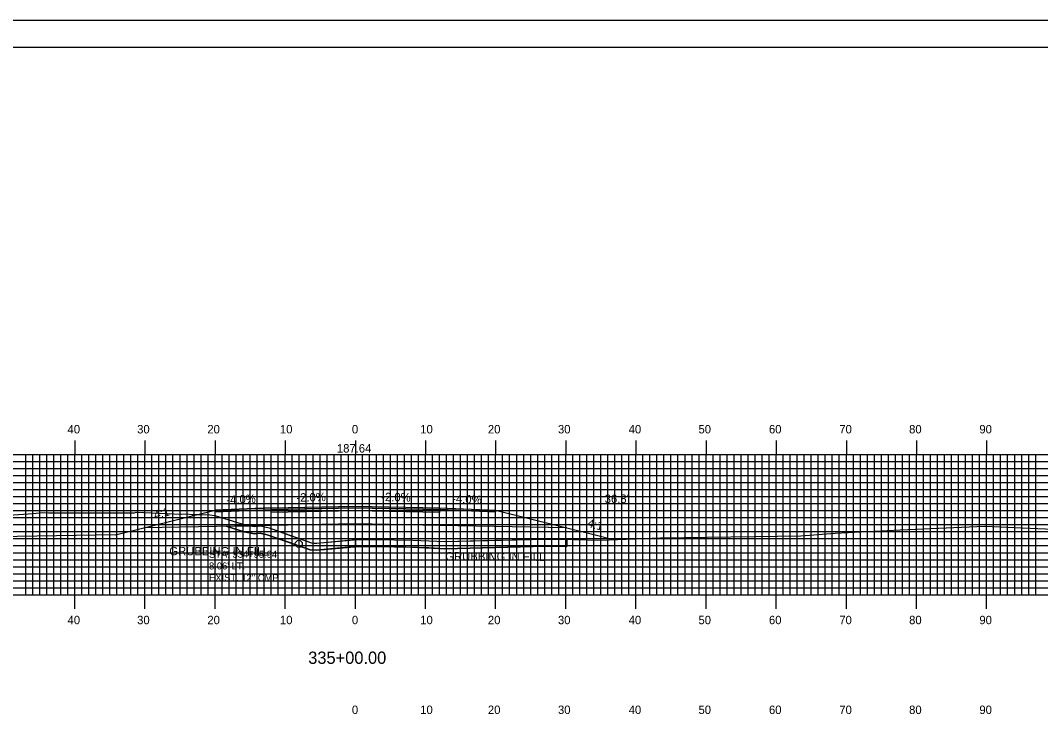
# Model space of a CAD drawing. Extents: x 1823179 to 1823522, y 442591 to 442811.
# Drawn here: x 1823297 to 1823442.5, y 442711.2 to 442810.5 of the extents above; entities that cross this region are included whole.
import ezdxf

# ---------------------------------------------------------------- set-up
doc = ezdxf.new("R2010")
doc.units = 0
for name, color, linetype in [('ANNOTATION', 7, 'Continuous'), ('BORDER', 7, 'Continuous'), ('D_Drainage_Culvert', 7, 'Continuous'), ('D_Roadway_Centerline', 7, 'Continuous'), ('D_Roadway_Centerline_Text', 7, 'Continuous'), ('D_Roadway_Edge_Shoulder', 7, 'Continuous'), ('D_Roadway_Edge_TW', 7, 'Continuous'), ('D_Roadway_FinishedGrade', 7, 'Continuous'), ('D_Roadway_Pavement', 7, 'Continuous'), ('D_Roadway_SlopeLines', 7, 'Continuous'), ('D_Roadway_SubGrade', 7, 'Continuous'), ('D_Text_Monospaced', 7, 'Continuous'), ('D_Text_Standard', 7, 'Continuous'), ('GRUBBING IN FILL', 7, 'Continuous'), ('H_V ANNOTATION', 7, 'Continuous'), ('MAJOR', 7, 'Continuous'), ('MINOR', 7, 'Continuous'), ('PLOT BOUNDARY', 7, 'Continuous'), ('S_Roadway_Centerline', 7, 'Continuous')]:
    doc.layers.add(name, color=color, linetype=linetype)

msp = doc.modelspace()

# ---------------------------------------------------------------- linework, layer by layer
at = {"layer": 'BORDER'}
msp.add_lwpolyline([(1823195.2, 442596.67), (1823515.2, 442596.67), (1823515.2, 442806.67), (1823195.2, 442806.67)], close=True, dxfattribs=at)
at = {"layer": 'D_Drainage_Culvert'}
msp.add_circle((1823336.74, 442735.93), 0.5, dxfattribs=at)
at = {"layer": 'D_Roadway_Centerline'}
msp.add_lwpolyline([(1823310.62, 442737.2), (1823314.62, 442738.2), (1823324.8, 442740.74), (1823332.8, 442741.06), (1823344.8, 442741.3), (1823356.8, 442741.06), (1823364.8, 442740.74), (1823374.97, 442738.2), (1823378.97, 442737.2), (1823381.61, 442736.54)], dxfattribs=at)
at = {"layer": 'D_Roadway_Edge_Shoulder'}
for points in [[(1823332.8, 442741.06), (1823324.8, 442740.74), (1823324.8, 442740.49), (1823332.8, 442740.81)], [(1823356.8, 442741.06), (1823364.8, 442740.74), (1823364.8, 442740.49), (1823356.8, 442740.81)]]:
    msp.add_lwpolyline(points, close=True, dxfattribs=at)
at = {"layer": 'D_Roadway_Edge_TW'}
msp.add_lwpolyline([(1823332.8, 442740.81), (1823332.8, 442741.06), (1823344.8, 442741.3), (1823356.8, 442741.06), (1823356.8, 442740.81), (1823344.8, 442741.05)], close=True, dxfattribs=at)
at = {"layer": 'D_Roadway_FinishedGrade'}
msp.add_line((1823310.62, 442737.2), (1823264.23, 442736.46), dxfattribs=at)
at = {"layer": 'D_Roadway_Pavement'}
msp.add_lwpolyline([(1823332.8, 442740.39), (1823332.8, 442740.81), (1823344.8, 442741.05), (1823356.8, 442740.81), (1823356.8, 442740.39), (1823344.8, 442740.63)], close=True, dxfattribs=at)
at = {"layer": 'D_Roadway_SlopeLines'}
msp.add_lwpolyline([(1823364.8, 442740.74), (1823378.97, 442737.2), (1823381.61, 442736.54)], dxfattribs=at)
at = {"layer": 'D_Roadway_SubGrade'}
msp.add_lwpolyline([(1823332.8, 442738.56), (1823314.62, 442738.2), (1823324.8, 442740.74), (1823324.8, 442740.49), (1823332.8, 442740.81), (1823344.8, 442741.05), (1823356.8, 442740.81), (1823364.8, 442740.49), (1823364.8, 442740.74), (1823374.97, 442738.2), (1823356.8, 442738.56), (1823344.8, 442738.8)], close=True, dxfattribs=at)
at = {"layer": 'GRUBBING IN FILL'}
msp.add_line((1823374.97, 442736.57), (1823374.97, 442735.57), dxfattribs=at)
msp.add_line((1823374.97, 442736.57), (1823374.97, 442735.57), dxfattribs=at)
for points in [[(1823326.37, 442738.43), (1823329.8, 442738.5), (1823330.47, 442738.38), (1823330.88, 442738.43), (1823331.29, 442738.48), (1823331.9, 442738.33), (1823332.51, 442738.19), (1823335.53, 442737.13), (1823338.55, 442736.06), (1823338.93, 442736.04), (1823339.32, 442736.01), (1823344.8, 442736.53), (1823344.8, 442735.53), (1823342.27, 442735.29), (1823339.33, 442735.01), (1823338.34, 442735.07), (1823335.29, 442736.15), (1823332.23, 442737.23), (1823331.23, 442737.46), (1823330.44, 442737.37), (1823328.97, 442737.63)], [(1823326.37, 442738.43), (1823329.8, 442738.5), (1823330.47, 442738.38), (1823330.88, 442738.43), (1823331.29, 442738.48), (1823331.9, 442738.33), (1823332.51, 442738.19), (1823335.53, 442737.13), (1823338.55, 442736.06), (1823338.93, 442736.04), (1823339.32, 442736.01), (1823344.8, 442736.53), (1823344.8, 442735.53), (1823342.27, 442735.29), (1823339.33, 442735.01), (1823338.34, 442735.07), (1823335.29, 442736.15), (1823332.23, 442737.23), (1823331.23, 442737.46), (1823330.44, 442737.37), (1823328.97, 442737.63)], [(1823344.8, 442736.53), (1823346.48, 442736.56), (1823350.4, 442736.5), (1823353, 442736.45), (1823355.28, 442736.35), (1823357.56, 442736.24), (1823364.75, 442736.43), (1823371.94, 442736.61), (1823374.04, 442736.6), (1823374.97, 442736.57), (1823374.97, 442735.57), (1823374.02, 442735.6), (1823371.95, 442735.61), (1823364.75, 442735.43), (1823357.55, 442735.24), (1823355.26, 442735.35), (1823350.38, 442735.5), (1823345.2, 442735.57), (1823344.8, 442735.53)], [(1823344.8, 442736.53), (1823346.48, 442736.56), (1823350.4, 442736.5), (1823353, 442736.45), (1823355.28, 442736.35), (1823357.56, 442736.24), (1823364.75, 442736.43), (1823371.94, 442736.61), (1823374.04, 442736.6), (1823374.97, 442736.57), (1823374.97, 442735.57), (1823374.02, 442735.6), (1823371.95, 442735.61), (1823364.75, 442735.43), (1823357.55, 442735.24), (1823355.26, 442735.35), (1823350.38, 442735.5), (1823345.2, 442735.57), (1823344.8, 442735.53)]]:
    msp.add_lwpolyline(points, close=True, dxfattribs=at)
msp.add_lwpolyline([(1823326.37, 442738.43), (1823328.97, 442737.63), (1823330.44, 442737.37), (1823331.23, 442737.46), (1823332.23, 442737.23), (1823338.34, 442735.07), (1823339.33, 442735.01), (1823345.2, 442735.57), (1823347.79, 442735.55), (1823352.97, 442735.45), (1823357.55, 442735.24), (1823371.95, 442735.61), (1823374.02, 442735.6), (1823374.97, 442735.57)], dxfattribs=at)
msp.add_lwpolyline([(1823326.37, 442738.43), (1823328.97, 442737.63), (1823330.44, 442737.37), (1823331.23, 442737.46), (1823332.23, 442737.23), (1823338.34, 442735.07), (1823339.33, 442735.01), (1823345.2, 442735.57), (1823347.79, 442735.55), (1823352.97, 442735.45), (1823357.55, 442735.24), (1823371.95, 442735.61), (1823374.02, 442735.6), (1823374.97, 442735.57)], dxfattribs=at)
at = {"layer": 'MAJOR'}
for p, q in [((1823304.8, 442750.67), (1823304.8, 442748.67)), ((1823314.8, 442750.67), (1823314.8, 442748.67)), ((1823324.8, 442750.67), (1823324.8, 442748.67)), ((1823334.8, 442750.67), (1823334.8, 442748.67)), ((1823344.8, 442750.67), (1823344.8, 442748.67)), ((1823354.8, 442750.67), (1823354.8, 442748.67)), ((1823364.8, 442750.67), (1823364.8, 442748.67)), ((1823374.8, 442750.67), (1823374.8, 442748.67)), ((1823384.8, 442750.67), (1823384.8, 442748.67)), ((1823394.8, 442750.67), (1823394.8, 442748.67)), ((1823404.8, 442750.67), (1823404.8, 442748.67)), ((1823414.8, 442750.67), (1823414.8, 442748.67)), ((1823424.8, 442750.67), (1823424.8, 442748.67)), ((1823434.8, 442750.67), (1823434.8, 442748.67)), ((1823204.8, 442748.67), (1823484.8, 442748.67)), ((1823204.8, 442748.67), (1823484.8, 442748.67)), ((1823304.8, 442728.67), (1823304.8, 442748.67)), ((1823314.8, 442728.67), (1823314.8, 442748.67)), ((1823324.8, 442728.67), (1823324.8, 442748.67)), ((1823334.8, 442728.67), (1823334.8, 442748.67)), ((1823344.8, 442728.67), (1823344.8, 442748.67)), ((1823354.8, 442728.67), (1823354.8, 442748.67)), ((1823364.8, 442728.67), (1823364.8, 442748.67)), ((1823374.8, 442728.67), (1823374.8, 442748.67)), ((1823384.8, 442728.67), (1823384.8, 442748.67)), ((1823394.8, 442728.67), (1823394.8, 442748.67)), ((1823404.8, 442728.67), (1823404.8, 442748.67)), ((1823414.8, 442728.67), (1823414.8, 442748.67)), ((1823424.8, 442728.67), (1823424.8, 442748.67)), ((1823434.8, 442728.67), (1823434.8, 442748.67)), ((1823204.8, 442743.67), (1823484.8, 442743.67)), ((1823204.8, 442738.67), (1823484.8, 442738.67)), ((1823204.8, 442733.67), (1823484.8, 442733.67)), ((1823204.8, 442728.67), (1823484.8, 442728.67)), ((1823204.8, 442728.67), (1823484.8, 442728.67)), ((1823304.8, 442726.66), (1823304.8, 442728.67)), ((1823314.8, 442726.66), (1823314.8, 442728.67)), ((1823324.8, 442726.66), (1823324.8, 442728.67)), ((1823334.8, 442726.66), (1823334.8, 442728.67)), ((1823344.8, 442726.66), (1823344.8, 442728.67)), ((1823354.8, 442726.66), (1823354.8, 442728.67)), ((1823364.8, 442726.66), (1823364.8, 442728.67)), ((1823374.8, 442726.66), (1823374.8, 442728.67)), ((1823384.8, 442726.66), (1823384.8, 442728.67)), ((1823394.8, 442726.66), (1823394.8, 442728.67)), ((1823404.8, 442726.66), (1823404.8, 442728.67)), ((1823414.8, 442726.66), (1823414.8, 442728.67)), ((1823424.8, 442726.66), (1823424.8, 442728.67)), ((1823434.8, 442726.66), (1823434.8, 442728.67))]:
    msp.add_line(p, q, dxfattribs=at)
at = {"layer": 'MINOR'}
for p, q in [((1823297.8, 442728.67), (1823297.8, 442748.67)), ((1823298.8, 442728.67), (1823298.8, 442748.67)), ((1823299.8, 442728.67), (1823299.8, 442748.67)), ((1823300.8, 442728.67), (1823300.8, 442748.67)), ((1823301.8, 442728.67), (1823301.8, 442748.67)), ((1823302.8, 442728.67), (1823302.8, 442748.67)), ((1823303.8, 442728.67), (1823303.8, 442748.67)), ((1823305.8, 442728.67), (1823305.8, 442748.67)), ((1823306.8, 442728.67), (1823306.8, 442748.67)), ((1823307.8, 442728.67), (1823307.8, 442748.67)), ((1823308.8, 442728.67), (1823308.8, 442748.67)), ((1823309.8, 442728.67), (1823309.8, 442748.67)), ((1823310.8, 442728.67), (1823310.8, 442748.67)), ((1823311.8, 442728.67), (1823311.8, 442748.67)), ((1823312.8, 442728.67), (1823312.8, 442748.67)), ((1823313.8, 442728.67), (1823313.8, 442748.67)), ((1823315.8, 442728.67), (1823315.8, 442748.67)), ((1823316.8, 442728.67), (1823316.8, 442748.67)), ((1823317.8, 442728.67), (1823317.8, 442748.67)), ((1823318.8, 442728.67), (1823318.8, 442748.67)), ((1823319.8, 442728.67), (1823319.8, 442748.67)), ((1823320.8, 442728.67), (1823320.8, 442748.67)), ((1823321.8, 442728.67), (1823321.8, 442748.67)), ((1823322.8, 442728.67), (1823322.8, 442748.67)), ((1823323.8, 442728.67), (1823323.8, 442748.67)), ((1823325.8, 442728.67), (1823325.8, 442748.67)), ((1823326.8, 442728.67), (1823326.8, 442748.67)), ((1823327.8, 442728.67), (1823327.8, 442748.67)), ((1823328.8, 442728.67), (1823328.8, 442748.67)), ((1823329.8, 442728.67), (1823329.8, 442748.67)), ((1823330.8, 442728.67), (1823330.8, 442748.67)), ((1823331.8, 442728.67), (1823331.8, 442748.67)), ((1823332.8, 442728.67), (1823332.8, 442748.67)), ((1823333.8, 442728.67), (1823333.8, 442748.67)), ((1823335.8, 442728.67), (1823335.8, 442748.67)), ((1823336.8, 442728.67), (1823336.8, 442748.67)), ((1823337.8, 442728.67), (1823337.8, 442748.67)), ((1823338.8, 442728.67), (1823338.8, 442748.67)), ((1823339.8, 442728.67), (1823339.8, 442748.67)), ((1823340.8, 442728.67), (1823340.8, 442748.67)), ((1823341.8, 442728.67), (1823341.8, 442748.67)), ((1823342.8, 442728.67), (1823342.8, 442748.67)), ((1823343.8, 442728.67), (1823343.8, 442748.67)), ((1823345.8, 442728.67), (1823345.8, 442748.67)), ((1823346.8, 442728.67), (1823346.8, 442748.67)), ((1823347.8, 442728.67), (1823347.8, 442748.67)), ((1823348.8, 442728.67), (1823348.8, 442748.67)), ((1823349.8, 442728.67), (1823349.8, 442748.67)), ((1823350.8, 442728.67), (1823350.8, 442748.67)), ((1823351.8, 442728.67), (1823351.8, 442748.67)), ((1823352.8, 442728.67), (1823352.8, 442748.67)), ((1823353.8, 442728.67), (1823353.8, 442748.67)), ((1823355.8, 442728.67), (1823355.8, 442748.67)), ((1823356.8, 442728.67), (1823356.8, 442748.67)), ((1823357.8, 442728.67), (1823357.8, 442748.67)), ((1823358.8, 442728.67), (1823358.8, 442748.67)), ((1823359.8, 442728.67), (1823359.8, 442748.67)), ((1823360.8, 442728.67), (1823360.8, 442748.67)), ((1823361.8, 442728.67), (1823361.8, 442748.67)), ((1823362.8, 442728.67), (1823362.8, 442748.67)), ((1823363.8, 442728.67), (1823363.8, 442748.67)), ((1823365.8, 442728.67), (1823365.8, 442748.67)), ((1823366.8, 442728.67), (1823366.8, 442748.67)), ((1823367.8, 442728.67), (1823367.8, 442748.67)), ((1823368.8, 442728.67), (1823368.8, 442748.67)), ((1823369.8, 442728.67), (1823369.8, 442748.67)), ((1823370.8, 442728.67), (1823370.8, 442748.67)), ((1823371.8, 442728.67), (1823371.8, 442748.67)), ((1823372.8, 442728.67), (1823372.8, 442748.67)), ((1823373.8, 442728.67), (1823373.8, 442748.67)), ((1823375.8, 442728.67), (1823375.8, 442748.67)), ((1823376.8, 442728.67), (1823376.8, 442748.67)), ((1823377.8, 442728.67), (1823377.8, 442748.67)), ((1823378.8, 442728.67), (1823378.8, 442748.67)), ((1823379.8, 442728.67), (1823379.8, 442748.67)), ((1823380.8, 442728.67), (1823380.8, 442748.67)), ((1823381.8, 442728.67), (1823381.8, 442748.67)), ((1823382.8, 442728.67), (1823382.8, 442748.67)), ((1823383.8, 442728.67), (1823383.8, 442748.67)), ((1823385.8, 442728.67), (1823385.8, 442748.67)), ((1823386.8, 442728.67), (1823386.8, 442748.67)), ((1823387.8, 442728.67), (1823387.8, 442748.67)), ((1823388.8, 442728.67), (1823388.8, 442748.67)), ((1823389.8, 442728.67), (1823389.8, 442748.67)), ((1823390.8, 442728.67), (1823390.8, 442748.67)), ((1823391.8, 442728.67), (1823391.8, 442748.67)), ((1823392.8, 442728.67), (1823392.8, 442748.67)), ((1823393.8, 442728.67), (1823393.8, 442748.67)), ((1823395.8, 442728.67), (1823395.8, 442748.67)), ((1823396.8, 442728.67), (1823396.8, 442748.67)), ((1823397.8, 442728.67), (1823397.8, 442748.67)), ((1823398.8, 442728.67), (1823398.8, 442748.67)), ((1823399.8, 442728.67), (1823399.8, 442748.67)), ((1823400.8, 442728.67), (1823400.8, 442748.67)), ((1823401.8, 442728.67), (1823401.8, 442748.67)), ((1823402.8, 442728.67), (1823402.8, 442748.67)), ((1823403.8, 442728.67), (1823403.8, 442748.67)), ((1823405.8, 442728.67), (1823405.8, 442748.67)), ((1823406.8, 442728.67), (1823406.8, 442748.67)), ((1823407.8, 442728.67), (1823407.8, 442748.67)), ((1823408.8, 442728.67), (1823408.8, 442748.67)), ((1823409.8, 442728.67), (1823409.8, 442748.67)), ((1823410.8, 442728.67), (1823410.8, 442748.67)), ((1823411.8, 442728.67), (1823411.8, 442748.67)), ((1823412.8, 442728.67), (1823412.8, 442748.67)), ((1823413.8, 442728.67), (1823413.8, 442748.67)), ((1823415.8, 442728.67), (1823415.8, 442748.67)), ((1823416.8, 442728.67), (1823416.8, 442748.67)), ((1823417.8, 442728.67), (1823417.8, 442748.67)), ((1823418.8, 442728.67), (1823418.8, 442748.67)), ((1823419.8, 442728.67), (1823419.8, 442748.67)), ((1823420.8, 442728.67), (1823420.8, 442748.67)), ((1823421.8, 442728.67), (1823421.8, 442748.67)), ((1823422.8, 442728.67), (1823422.8, 442748.67)), ((1823423.8, 442728.67), (1823423.8, 442748.67)), ((1823425.8, 442728.67), (1823425.8, 442748.67)), ((1823426.8, 442728.67), (1823426.8, 442748.67)), ((1823427.8, 442728.67), (1823427.8, 442748.67)), ((1823428.8, 442728.67), (1823428.8, 442748.67)), ((1823429.8, 442728.67), (1823429.8, 442748.67)), ((1823430.8, 442728.67), (1823430.8, 442748.67)), ((1823431.8, 442728.67), (1823431.8, 442748.67)), ((1823432.8, 442728.67), (1823432.8, 442748.67)), ((1823433.8, 442728.67), (1823433.8, 442748.67)), ((1823435.8, 442728.67), (1823435.8, 442748.67)), ((1823436.8, 442728.67), (1823436.8, 442748.67)), ((1823437.8, 442728.67), (1823437.8, 442748.67)), ((1823438.8, 442728.67), (1823438.8, 442748.67)), ((1823439.8, 442728.67), (1823439.8, 442748.67)), ((1823440.8, 442728.67), (1823440.8, 442748.67)), ((1823441.8, 442728.67), (1823441.8, 442748.67)), ((1823204.8, 442747.67), (1823484.8, 442747.67)), ((1823204.8, 442746.67), (1823484.8, 442746.67)), ((1823204.8, 442745.67), (1823484.8, 442745.67)), ((1823204.8, 442744.67), (1823484.8, 442744.67)), ((1823204.8, 442742.67), (1823484.8, 442742.67)), ((1823204.8, 442741.67), (1823484.8, 442741.67)), ((1823204.8, 442740.67), (1823484.8, 442740.67)), ((1823204.8, 442739.67), (1823484.8, 442739.67)), ((1823204.8, 442737.67), (1823484.8, 442737.67)), ((1823204.8, 442736.67), (1823484.8, 442736.67)), ((1823204.8, 442735.67), (1823484.8, 442735.67)), ((1823204.8, 442734.67), (1823484.8, 442734.67)), ((1823204.8, 442732.67), (1823484.8, 442732.67)), ((1823204.8, 442731.67), (1823484.8, 442731.67)), ((1823204.8, 442730.67), (1823484.8, 442730.67)), ((1823204.8, 442729.67), (1823484.8, 442729.67))]:
    msp.add_line(p, q, dxfattribs=at)
at = {"layer": 'PLOT BOUNDARY'}
msp.add_lwpolyline([(1823179.01, 442590.55), (1823519.01, 442590.55), (1823519.01, 442810.55), (1823179.01, 442810.55)], close=True, dxfattribs=at)
at = {"layer": 'S_Roadway_Centerline'}
msp.add_lwpolyline([(1823294.66, 442739.97), (1823298.87, 442740.23), (1823300.14, 442740.4), (1823301.04, 442740.37), (1823309.53, 442740.33), (1823313.29, 442740.36), (1823313.55, 442740.46), (1823314.64, 442740.4), (1823320, 442740.18), (1823320.79, 442740.19), (1823321.48, 442740.1), (1823322.3, 442740.1), (1823324.03, 442740.06), (1823324.76, 442739.98), (1823329.21, 442738.6), (1823330.47, 442738.38), (1823331.29, 442738.48), (1823332.51, 442738.19), (1823338.55, 442736.06), (1823339.32, 442736.01), (1823345.16, 442736.57), (1823347.8, 442736.55), (1823353, 442736.45), (1823357.56, 442736.24), (1823371.94, 442736.61), (1823374.04, 442736.6), (1823379.74, 442736.47), (1823388.31, 442736.8), (1823408.33, 442737.07), (1823413.2, 442737.45), (1823422.47, 442737.91), (1823434.48, 442738.44), (1823447.5, 442737.89)], dxfattribs=at)

# ---------------------------------------------------------------- texts
at = {"layer": 'ANNOTATION'}
for s, rotation, p in [('-4.0%', 2.2906, (1823326.43, 442741.61)), ('-2.0%', 1.1458, (1823336.4, 442741.93)), ('-2.0%', 358.8542, (1823348.48, 442742.03)), ('-4.0%', 357.7094, (1823358.59, 442741.79)), ('4:1', 14.0362, (1823316.24, 442739.46)), ('4:1', 345.9638, (1823377.79, 442738.35))]:
    msp.add_text(s, height=1.2, rotation=rotation, dxfattribs=at).set_placement(p)
at = {"layer": 'D_Roadway_Centerline'}
for s, p in [('C', (1823344.79, 442741.3)), ('L', (1823344.8, 442741.29))]:
    msp.add_text(s, height=0.0146, dxfattribs=at).set_placement(p)
at = {"layer": 'D_Roadway_Centerline_Text'}
msp.add_text('187.64', height=1.2, dxfattribs=at).set_placement((1823342.17, 442748.94))
at = {"layer": 'D_Text_Monospaced'}
for s, p in [('STA. 334+95.94', (1823323.94, 442733.94)), ("8.06' LT.", (1823323.94, 442732.28)), ('EXIST. 12" CMP', (1823323.94, 442730.6))]:
    msp.add_text(s, height=1, dxfattribs=at).set_placement(p)
at = {"layer": 'D_Text_Standard'}
msp.add_text("36.8'", height=1.2, dxfattribs=at).set_placement((1823380.35, 442741.76))
at = {"layer": 'GRUBBING IN FILL'}
for p in [(1823318.28, 442734.3), (1823357.62, 442733.55)]:
    msp.add_text('GRUBBING IN FILL', height=1.2, rotation=359.8053, dxfattribs=at).set_placement(p)
at = {"layer": 'H_V ANNOTATION'}
for s, height, p in [('40', 1.2, (1823303.77, 442751.67)), ('30', 1.2, (1823313.69, 442751.67)), ('20', 1.2, (1823323.7, 442751.67)), ('10', 1.2, (1823334.05, 442751.67)), ('0', 1.2, (1823344.31, 442751.67)), ('10', 1.2, (1823354.05, 442751.67)), ('20', 1.2, (1823363.7, 442751.67)), ('30', 1.2, (1823373.69, 442751.67)), ('40', 1.2, (1823383.77, 442751.67)), ('50', 1.2, (1823393.72, 442751.67)), ('60', 1.2, (1823403.77, 442751.67)), ('70', 1.2, (1823413.8, 442751.67)), ('80', 1.2, (1823423.75, 442751.67)), ('90', 1.2, (1823433.77, 442751.67)), ('40', 1.2, (1823303.77, 442724.47)), ('30', 1.2, (1823313.69, 442724.47)), ('20', 1.2, (1823323.7, 442724.47)), ('10', 1.2, (1823334.05, 442724.47)), ('0', 1.2, (1823344.31, 442724.47)), ('10', 1.2, (1823354.05, 442724.47)), ('20', 1.2, (1823363.7, 442724.47)), ('30', 1.2, (1823373.69, 442724.47)), ('40', 1.2, (1823383.77, 442724.47)), ('50', 1.2, (1823393.72, 442724.47)), ('60', 1.2, (1823403.77, 442724.47)), ('70', 1.2, (1823413.8, 442724.47)), ('80', 1.2, (1823423.75, 442724.47)), ('90', 1.2, (1823433.77, 442724.47)), ('335+00.00', 1.75, (1823338.08, 442718.82)), ('0', 1.2, (1823344.31, 442711.67)), ('10', 1.2, (1823354.05, 442711.67)), ('20', 1.2, (1823363.7, 442711.67)), ('30', 1.2, (1823373.69, 442711.67)), ('40', 1.2, (1823383.77, 442711.67)), ('50', 1.2, (1823393.72, 442711.67)), ('60', 1.2, (1823403.77, 442711.67)), ('70', 1.2, (1823413.8, 442711.67)), ('80', 1.2, (1823423.75, 442711.67)), ('90', 1.2, (1823433.77, 442711.67))]:
    msp.add_text(s, height=height, dxfattribs=at).set_placement(p)
at = {"layer": 'S_Roadway_Centerline'}
for s in ['C', 'L']:
    msp.add_text(s, height=0.0146, dxfattribs=at).set_placement((1823300.13, 442740.4))

doc.saveas('drawing.dxf')
